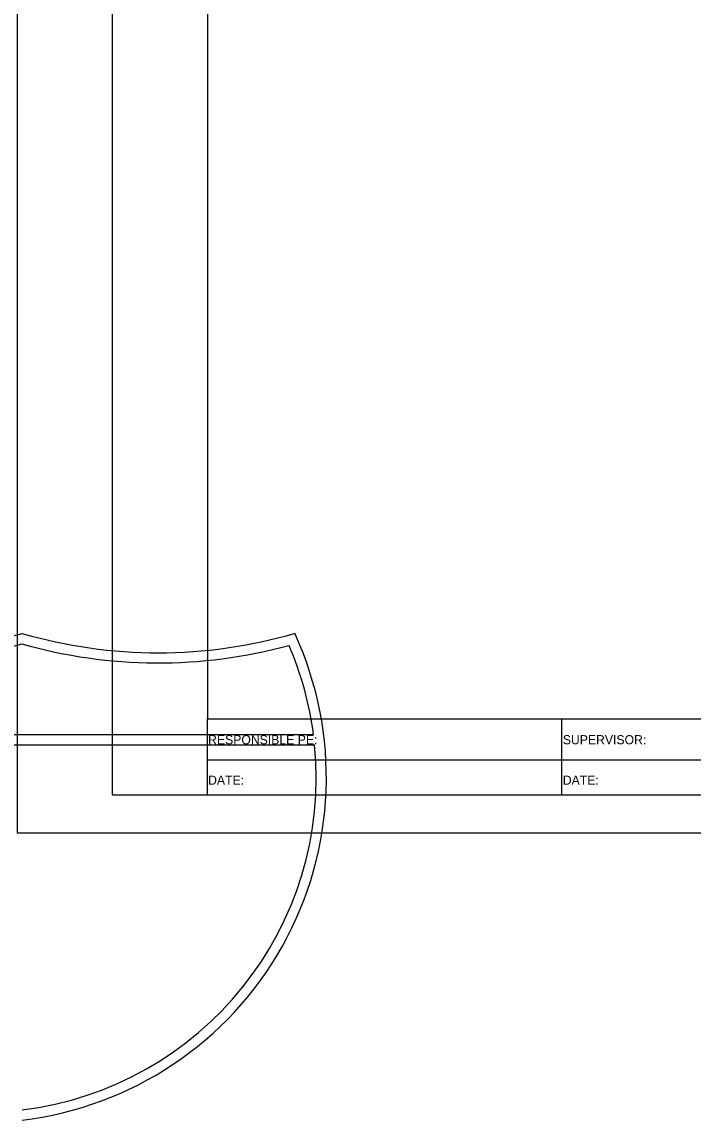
# Model space of a CAD drawing. Extents: x 1797809 to 2198143, y 249608 to 1237864.
# Drawn here: x 2195550.3 to 2195638.5, y 1237080.3 to 1237224.6 of the extents above; entities that cross this region are included whole.
import ezdxf

# ---------------------------------------------------------------- set-up
doc = ezdxf.new("R2010")
doc.units = 0
for name, color, linetype in [('GSCOLORFILL', 7, 'Continuous'), ('GSOUTLINE', 7, 'Continuous'), ('GSSHT', 7, 'Continuous'), ('Level 45', 7, 'Continuous')]:
    doc.layers.add(name, color=color, linetype=linetype)

msp = doc.modelspace()

# ---------------------------------------------------------------- linework, layer by layer
at = {"layer": 'GSCOLORFILL'}
for p, q in [((2195574.71, 1237123.04), (2195574.71, 1237133.05)), ((2195621.23, 1237133.05), (2195621.23, 1237123.04)), ((2195574.71, 1237127.65), (2195730.33, 1237127.65))]:
    msp.add_line(p, q, dxfattribs=at)
msp.add_lwpolyline([(2195562.21, 1237123.04), (2195884.71, 1237123.04), (2195884.71, 1237333.04), (2195562.21, 1237333.04)], close=True, dxfattribs=at)
at = {"layer": 'GSOUTLINE'}
for points in [[(2195588.64, 1237130.95), (2195512.06, 1237130.95)], [(2195511.9, 1237129.61), (2195588.79, 1237129.61)]]:
    msp.add_lwpolyline(points, dxfattribs=at)
for centre, major_axis, start_param, end_param in [((2195532.44, 1237205.68), (63.98, 0), 4.428637, 4.996141), ((2195568.26, 1237205.68), (63.98, 0), 4.428637, 4.996141), ((2195545.02, 1237125.3), (45.32, 0), 4.830309, 6.715209), ((2195532.44, 1237205.68), (65.31, 0), 4.446475, 4.990194), ((2195568.26, 1237205.68), (65.31, 0), 4.434584, 4.978303), ((2195545.02, 1237125.3), (43.99, 0), 0.128722, 0.406196), ((2195545.02, 1237125.3), (43.99, 0), 4.8339, 6.381407)]:
    msp.add_ellipse(centre, major_axis=major_axis, ratio=0.999829, start_param=start_param, end_param=end_param, dxfattribs=at)
at = {"layer": 'GSSHT'}
msp.add_lwpolyline([(2195549.71, 1237118.04), (2195889.71, 1237118.04), (2195889.71, 1237338.04), (2195549.71, 1237338.04)], close=True, dxfattribs=at)
at = {"layer": 'Level 45'}
msp.add_lwpolyline([(2195574.71, 1237133.05), (2195874.71, 1237133.05), (2195874.71, 1237323.05), (2195574.71, 1237323.05)], close=True, dxfattribs=at)

# ---------------------------------------------------------------- texts
at = {"layer": 'GSOUTLINE'}
for s, p in [('RESPONSIBLE PE:', (2195574.8, 1237129.69)), ('SUPERVISOR:', (2195621.4, 1237129.69)), ('DATE:', (2195574.8, 1237124.37)), ('DATE:', (2195621.4, 1237124.37))]:
    msp.add_text(s, height=1.2, rotation=360, dxfattribs=at).set_placement(p)

doc.saveas('drawing.dxf')
